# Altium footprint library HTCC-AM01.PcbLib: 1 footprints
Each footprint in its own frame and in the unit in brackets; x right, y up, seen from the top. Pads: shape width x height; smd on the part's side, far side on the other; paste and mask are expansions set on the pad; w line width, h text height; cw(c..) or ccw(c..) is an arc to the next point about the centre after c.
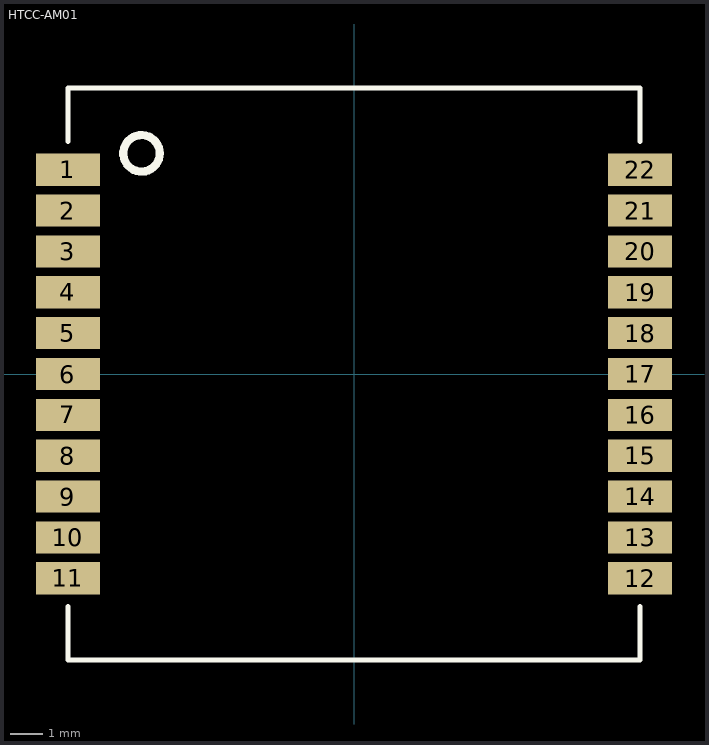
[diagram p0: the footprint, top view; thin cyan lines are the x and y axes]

## HTCC-AM01 [mm]
pads (22):
  rect 2x1 smd: 1(-8.89,6.35) 2(-8.89,5.08) 3(-8.89,3.81) 4(-8.89,2.54) 5(-8.89,1.27) 6(-8.89,0) 7(-8.89,-1.27) 8(-8.89,-2.54) 9(-8.89,-3.81) 10(-8.89,-5.08) 11(-8.89,-6.35) 12(8.89,-6.35) 13(8.89,-5.08) 14(8.89,-3.81) 15(8.89,-2.54) 16(8.89,-1.27) 17(8.89,0) 18(8.89,1.27) 19(8.89,2.54) 20(8.89,3.81) 21(8.89,5.08) 22(8.89,6.35)
Top Overlay:
  circle w0.254: c-6.604,6.858 r0.568
  lines w0.152: -8.89,-7.222 -8.89,-8.89 8.89,-8.89 8.89,-7.222 ; -8.89,7.222 -8.89,8.89 8.89,8.89 8.89,7.222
